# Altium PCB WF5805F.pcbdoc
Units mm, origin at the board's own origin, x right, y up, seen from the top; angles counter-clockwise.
Board outline 17.7 x 17.26 mm, 2 copper layers (Top Layer, Bottom Layer); 1 components, 0 nets, 4 pads, 0 vias.
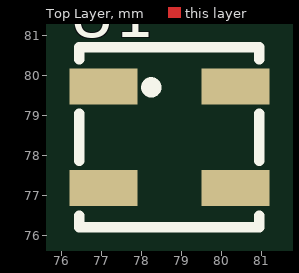
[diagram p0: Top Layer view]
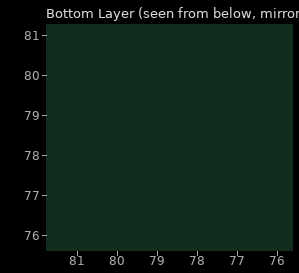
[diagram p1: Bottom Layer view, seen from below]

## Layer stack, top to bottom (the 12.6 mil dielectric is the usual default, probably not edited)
Top Layer: signal copper (thickness not stored)
Dielectric: dielectric 0.32, FR-4, Dk 4.8
Bottom Layer: signal copper (thickness not stored)

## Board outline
87.55,69.85 69.85,69.85 69.85,87.11 87.55,87.11

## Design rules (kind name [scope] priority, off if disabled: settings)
BoardOutlineClearance copperThickness1oz [All] p0: genericclearance=0.254 ignorepadtopadclearanceinfootprint=FALSE except(0: Arc-SplitContinuation Track-SplitContinuation SMDPad-SplitContinuation THPad-SplitContinuation Via-SplitContinuation Fill-SplitContinuation Poly-SplitContinuation Region-SplitContinuation Text-SplitContinuation; 0.152: Track-CutoutEdge SMDPad-CutoutEdge THPad-CutoutEdge Via-CutoutEdge Region-CutoutEdge; 0.3: Track-OutlineEdge SMDPad-OutlineEdge THPad-OutlineEdge Via-OutlineEdge Fill-OutlineEdge Region-OutlineEdge Poly-OutlineEdge Text-OutlineEdge Fill-CutoutEdge)
BoardOutlineClearance copperThickness2oz [All] p0: genericclearance=0.254 ignorepadtopadclearanceinfootprint=FALSE except(0: Arc-SplitContinuation Track-SplitContinuation SMDPad-SplitContinuation THPad-SplitContinuation Via-SplitContinuation Fill-SplitContinuation Poly-SplitContinuation Region-SplitContinuation Text-SplitContinuation; 0.152: Track-CutoutEdge SMDPad-CutoutEdge THPad-CutoutEdge Via-CutoutEdge Region-CutoutEdge; 0.3: Track-OutlineEdge SMDPad-OutlineEdge THPad-OutlineEdge Via-OutlineEdge Fill-OutlineEdge Region-OutlineEdge Poly-OutlineEdge Text-OutlineEdge Fill-CutoutEdge)
Clearance copperThickness1oz [All] p1: gap=0.178 ignorepadtopadclearanceinfootprint=FALSE except(0.102: Track-Track; 0.152: Track-SMDPad SMDPad-SMDPad Track-THPad SMDPad-THPad THPad-THPad Track-Via SMDPad-Via THPad-Via Via-Via SMDPad-Fill THPad-Fill Via-Fill Fill-Fill Track-Region SMDPad-Region THPad-Region Via-Region Region-Region Track-Poly SMDPad-Poly THPad-Poly Via-Poly Fill-Poly Region-Poly Poly-Poly Track-Text SMDPad-Text THPad-Text Via-Text Fill-Text Region-Text Poly-Text Text-Text; 0.175: Track-Hole SMDPad-Hole THPad-Hole Via-Hole Fill-Hole Region-Hole Poly-Hole Text-Hole Sheet-Hole; 0.3: Track-Fill Fill-Region Track-Sheet SMDPad-Sheet THPad-Sheet Via-Sheet Fill-Sheet Region-Sheet Poly-Sheet Text-Sheet)
Clearance copperThickness2oz [All] p1: gap=0.178 ignorepadtopadclearanceinfootprint=FALSE except(0.152: Track-SMDPad SMDPad-SMDPad Track-THPad SMDPad-THPad THPad-THPad Track-Via SMDPad-Via THPad-Via Via-Via SMDPad-Fill THPad-Fill Via-Fill Fill-Fill Track-Region SMDPad-Region THPad-Region Via-Region Region-Region Track-Poly SMDPad-Poly THPad-Poly Via-Poly Fill-Poly Region-Poly Poly-Poly Track-Text SMDPad-Text THPad-Text Via-Text Fill-Text Region-Text Poly-Text Text-Text; 0.175: Track-Hole SMDPad-Hole THPad-Hole Via-Hole Fill-Hole Region-Hole Poly-Hole Text-Hole Sheet-Hole; 0.203: Track-Track; 0.3: Track-Fill Fill-Region Track-Sheet SMDPad-Sheet THPad-Sheet Via-Sheet Fill-Sheet Region-Sheet Poly-Sheet Text-Sheet)
DiffPairsRouting differentialPair [All] p1: maxuncoupledlength=10 minlimit=6 maxlimit=6 mostfreqgap=6 toplayer_minwidth=5 toplayer_prefwidth=10 toplayer_maxwidth=100 bottomlayer_minwidth=5 bottomlayer_prefwidth=10 bottomlayer_maxwidth=100
PasteMaskExpansion pasteMaskExpansion [All] p1: expansion=0
PlaneConnect innerPlane [All] p1: planeconnectstyle=Relief reliefexpansion=0.508 reliefentries=4 reliefconductorwidth=0.254 reliefairgap=0.254
PolygonConnect copperRegion [All] p1: connectstyle=Relief reliefentries=4 reliefconductorwidth=10 polygonreliefangle="90 Angle" airgapwidth=10
RoutingVias viaSize [All] p1: viastyle="Through Hole" holewidth=12.0078 minholewidth=11.811 maxholewidth=248.0314 width=24.0158 minwidth=19.685 maxwidth=393.7008
SolderMaskExpansion solderMaskExpansion [All] p1: useseparateexpansions=TRUE expansion=2 expansionbottom=2
Width copperThickness1oz [All] p1: maxlimit=100 minlimit=5 preferedwidth=10
Width copperThickness2oz [All] p1: maxlimit=100 minlimit=8 preferedwidth=10

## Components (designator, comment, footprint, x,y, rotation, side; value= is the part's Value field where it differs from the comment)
U1 "WF5805F" SENSOR-SMD_4P-L4.5-W4.5_WF5805F 78.7,78.45 r0 top

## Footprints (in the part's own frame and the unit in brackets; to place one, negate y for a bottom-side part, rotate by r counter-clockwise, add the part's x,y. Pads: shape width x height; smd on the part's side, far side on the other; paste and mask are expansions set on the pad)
SENSOR-SMD_4P-L4.5-W4.5_WF5805F [mm]
  rect 1.7x0.9 smd: 1(-1.65,1.27) 2(-1.65,-1.27) 3(1.65,-1.27) 4(1.65,1.27)
  silkscreen extent -2.25,-2.25 2.25,2.25

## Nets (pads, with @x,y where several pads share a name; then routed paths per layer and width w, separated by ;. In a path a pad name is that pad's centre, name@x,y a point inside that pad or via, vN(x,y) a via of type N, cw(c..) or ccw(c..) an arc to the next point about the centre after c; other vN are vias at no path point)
pads on no net: U1.1 U1.2 U1.3 U1.4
